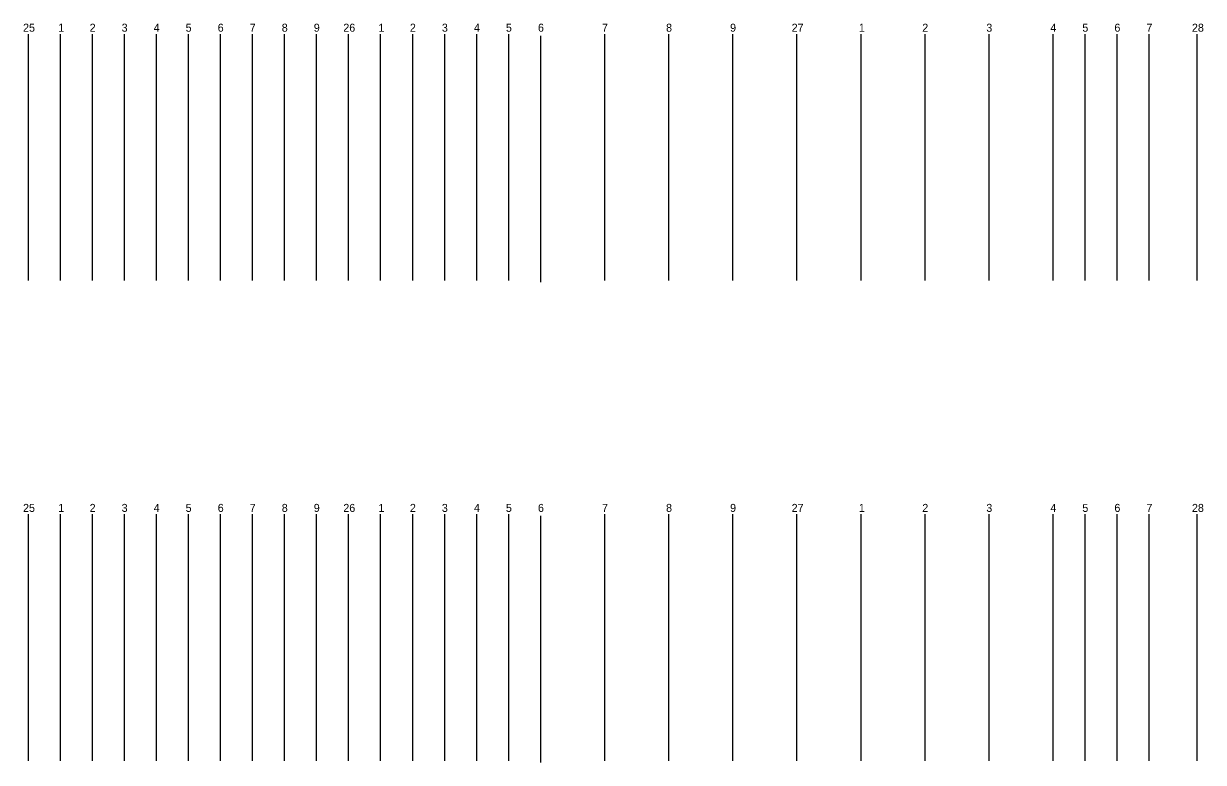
# Model space of a CAD drawing. Extents: x 2343 to 7744, y -6590 to 2050.
# Drawn here: x 5717 to 6454, y -5455 to -4993 of the extents above; entities that cross this region are included whole.
import ezdxf

# ---------------------------------------------------------------- set-up
doc = ezdxf.new("R2010")
doc.units = 0
doc.layers.add('Vrstva 1', color=7, linetype='Continuous')

msp = doc.modelspace()

# ---------------------------------------------------------------- linework, layer by layer
for p, q in [((5720, -5000), (5720, -5154)), ((5740, -5000), (5740, -5154)), ((5760, -5000), (5760, -5154)), ((5780, -5000), (5780, -5154)), ((5800, -5000), (5800, -5154)), ((5800, -5000), (5800, -5154)), ((5820, -5000), (5820, -5154)), ((5840, -5000), (5840, -5154)), ((5860, -5000), (5860, -5154)), ((5880, -5000), (5880, -5154)), ((5900, -5000), (5900, -5154)), ((5920, -5000), (5920, -5154)), ((5940, -5000), (5940, -5154)), ((5960, -5000), (5960, -5154)), ((5980, -5000), (5980, -5154)), ((6000, -5000), (6000, -5154)), ((6020, -5000), (6020, -5154)), ((6040, -5001), (6040, -5155)), ((6080, -5000), (6080, -5154)), ((6120, -5000), (6120, -5154)), ((6160, -5000), (6160, -5154)), ((6200, -5000), (6200, -5154)), ((6240, -5000), (6240, -5154)), ((6280, -5000), (6280, -5154)), ((6320, -5000), (6320, -5154)), ((6360, -5000), (6360, -5154)), ((6380, -5000), (6380, -5154)), ((6400, -5000), (6400, -5154)), ((6420, -5000), (6420, -5154)), ((6450, -5000), (6450, -5154)), ((5720, -5300), (5720, -5454)), ((5740, -5300), (5740, -5454)), ((5760, -5300), (5760, -5454)), ((5780, -5300), (5780, -5454)), ((5800, -5300), (5800, -5454)), ((5800, -5300), (5800, -5454)), ((5820, -5300), (5820, -5454)), ((5840, -5300), (5840, -5454)), ((5860, -5300), (5860, -5454)), ((5880, -5300), (5880, -5454)), ((5900, -5300), (5900, -5454)), ((5920, -5300), (5920, -5454)), ((5940, -5300), (5940, -5454)), ((5960, -5300), (5960, -5454)), ((5980, -5300), (5980, -5454)), ((6000, -5300), (6000, -5454)), ((6020, -5300), (6020, -5454)), ((6040, -5301), (6040, -5455)), ((6080, -5300), (6080, -5454)), ((6120, -5300), (6120, -5454)), ((6160, -5300), (6160, -5454)), ((6200, -5300), (6200, -5454)), ((6240, -5300), (6240, -5454)), ((6280, -5300), (6280, -5454)), ((6320, -5300), (6320, -5454)), ((6360, -5300), (6360, -5454)), ((6380, -5300), (6380, -5454)), ((6400, -5300), (6400, -5454)), ((6420, -5300), (6420, -5454)), ((6450, -5300), (6450, -5454))]:
    msp.add_line(p, q)

# ---------------------------------------------------------------- texts
at = {"layer": 'Vrstva 1'}
for s, p in [('25', (5716.88, -4998.5)), ('1', (5738.84, -4998.5)), ('2', (5758.47, -4998.5)), ('3', (5778.45, -4998.5)), ('4', (5798.46, -4998.5)), ('5', (5818.43, -4998.5)), ('6', (5838.45, -4998.5)), ('7', (5858.45, -4998.5)), ('8', (5878.45, -4998.5)), ('9', (5898.45, -4998.5)), ('26', (5916.89, -4998.5)), ('1', (5938.84, -4998.5)), ('2', (5958.47, -4998.5)), ('3', (5978.45, -4998.5)), ('4', (5998.46, -4998.5)), ('5', (6018.43, -4998.5)), ('6', (6038.45, -4998.5)), ('7', (6078.45, -4998.5)), ('8', (6118.45, -4998.5)), ('9', (6158.45, -4998.5)), ('27', (6196.89, -4998.5)), ('1', (6238.84, -4998.5)), ('2', (6278.47, -4998.5)), ('3', (6318.45, -4998.5)), ('4', (6358.46, -4998.5)), ('5', (6378.43, -4998.5)), ('6', (6398.45, -4998.5)), ('7', (6418.45, -4998.5)), ('28', (6446.89, -4998.5)), ('25', (5716.88, -5298.5)), ('1', (5738.84, -5298.5)), ('2', (5758.47, -5298.5)), ('3', (5778.45, -5298.5)), ('4', (5798.46, -5298.5)), ('5', (5818.43, -5298.5)), ('6', (5838.45, -5298.5)), ('7', (5858.45, -5298.5)), ('8', (5878.45, -5298.5)), ('9', (5898.45, -5298.5)), ('26', (5916.89, -5298.5)), ('1', (5938.84, -5298.5)), ('2', (5958.47, -5298.5)), ('3', (5978.45, -5298.5)), ('4', (5998.46, -5298.5)), ('5', (6018.43, -5298.5)), ('6', (6038.45, -5298.5)), ('7', (6078.45, -5298.5)), ('8', (6118.45, -5298.5)), ('9', (6158.45, -5298.5)), ('27', (6196.89, -5298.5)), ('1', (6238.84, -5298.5)), ('2', (6278.47, -5298.5)), ('3', (6318.45, -5298.5)), ('4', (6358.46, -5298.5)), ('5', (6378.43, -5298.5)), ('6', (6398.45, -5298.5)), ('7', (6418.45, -5298.5)), ('28', (6446.89, -5298.5))]:
    msp.add_text(s, height=5, dxfattribs=at).set_placement(p)

doc.saveas('drawing.dxf')
